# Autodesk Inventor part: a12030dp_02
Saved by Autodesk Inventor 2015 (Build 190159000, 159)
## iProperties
Created: 2022-06
Part Number: a12030dp_02
Checked By: TraceParts S.A.
Material: Générique
Catalog Web Link: www.traceparts.com
Document SubType Name: Modeling
Designer: TraceParts
Density: 1 g/cm^3
Appearance: Par défaut
Company: TraceParts S.A.
Author: TraceParts
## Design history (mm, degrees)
feature "a12030dp_02.ipt"
node "Solide1"
